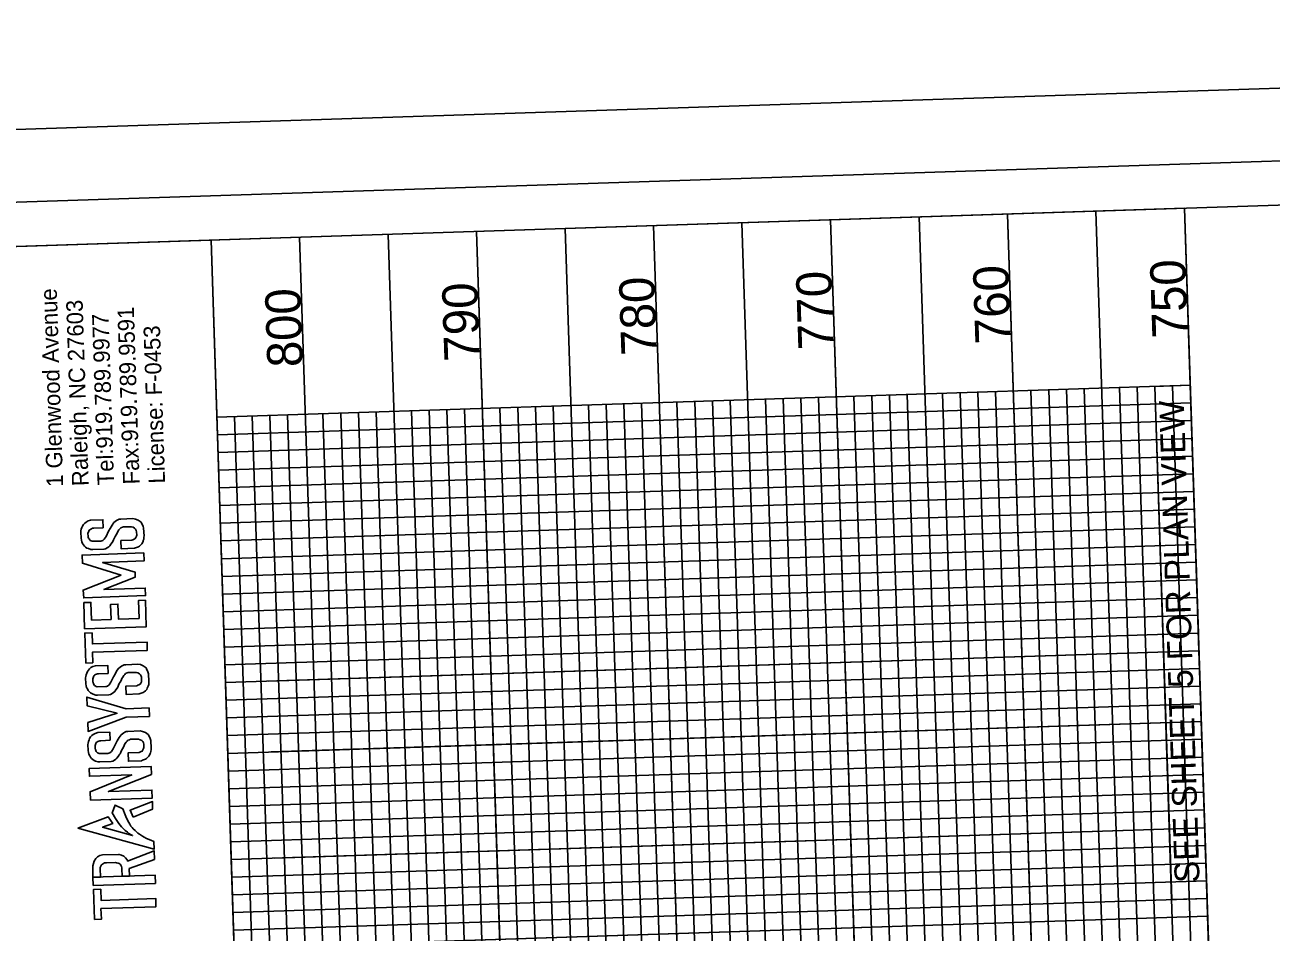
# Model space of a CAD drawing. Extents: x 1627314 to 1628469, y 762309 to 764253.
# Drawn here: x 1627512.6 to 1627864.5, y 763788.2 to 764044.4 of the extents above; entities that cross this region are included whole.
import ezdxf

# ---------------------------------------------------------------- set-up
doc = ezdxf.new("R2010")
doc.units = 0
for name, color, linetype in [('Exist Vertical Profile Vertical Axis Label', 7, 'Continuous'), ('Old_Level_2', 7, 'Continuous'), ('Old_Level_58', 7, 'Continuous'), ('Prop DSN Text', 7, 'Continuous'), ('Prop Grid Mask', 7, 'Continuous'), ('Sheet DOT Grid CELL', 7, 'Continuous'), ('Sheet Layout Profile Border Port 1', 7, 'Continuous'), ('Sheet Plot Border Inside CELL', 7, 'Continuous'), ('Sheet Plot Border Outside CELL', 7, 'Continuous'), ('Sheet Profile CELL', 7, 'Continuous'), ('Sheet Profile Grid Major CELL', 7, 'Continuous'), ('Sheet Profile Grid Middle CELL', 7, 'Continuous'), ('Sheet Profile Grid Minor CELL', 7, 'Continuous')]:
    doc.layers.add(name, color=color, linetype=linetype)

msp = doc.modelspace()

# ---------------------------------------------------------------- linework, layer by layer
at = {"layer": 'Old_Level_2'}
for points in [[(1627534.7, 763902.32), (1627534.62, 763904.63), (1627531.15, 763904.51), (1627530.45, 763904.29), (1627529.87, 763903.99), (1627529.49, 763903.68), (1627529.15, 763903.3), (1627528.88, 763902.85), (1627528.72, 763902.42), (1627528.72, 763902.42), (1627528.54, 763901.95), (1627528.44, 763901.47), (1627528.37, 763901.14), (1627528.46, 763899.4), (1627528.57, 763898.87), (1627528.66, 763898.42), (1627528.92, 763897.96), (1627529.14, 763897.57), (1627529.44, 763897.18), (1627529.76, 763896.88), (1627530.13, 763896.65), (1627530.53, 763896.47), (1627531.24, 763896.24), (1627531.76, 763896.2), (1627534.92, 763896.31), (1627535.4, 763896.44), (1627535.88, 763896.68), (1627536.28, 763896.99), (1627536.58, 763897.29), (1627536.92, 763897.76), (1627537.25, 763898.22), (1627537.46, 763898.51), (1627537.67, 763899), (1627537.88, 763899.49), (1627538.12, 763899.89), (1627538.39, 763900.34), (1627538.64, 763900.87), (1627538.84, 763901.31), (1627539.14, 763901.75), (1627539.43, 763902.07), (1627539.66, 763902.33), (1627540.13, 763902.5), (1627540.43, 763902.6), (1627542.67, 763902.64), (1627543.16, 763902.5), (1627543.58, 763902.27), (1627543.88, 763901.95), (1627544.06, 763901.6), (1627544.14, 763901.26), (1627544.19, 763900.3), (1627544.11, 763899.97), (1627543.93, 763899.64), (1627543.75, 763899.3), (1627543.42, 763899.15), (1627543.09, 763899), (1627542.82, 763898.88), (1627539.71, 763898.74), (1627539.82, 763896.4), (1627543.52, 763896.57), (1627543.8, 763896.69), (1627544.65, 763896.99), (1627544.94, 763897.18), (1627545.25, 763897.44), (1627545.61, 763897.83), (1627545.8, 763898.14), (1627545.96, 763898.58), (1627546.03, 763898.74), (1627546.19, 763899.18), (1627546.23, 763899.72), (1627546.25, 763900.11), (1627546.13, 763902.25), (1627545.97, 763902.84), (1627545.57, 763903.65), (1627545.43, 763903.93), (1627544.62, 763904.52), (1627543.83, 763904.83), (1627543.11, 763904.96), (1627539.69, 763904.8), (1627539.22, 763904.77), (1627538.85, 763904.63), (1627538.5, 763904.43), (1627537.76, 763903.86), (1627537.23, 763903.14), (1627536.68, 763902.14), (1627536.26, 763901.39), (1627535.54, 763899.9), (1627535.01, 763899.13), (1627534.59, 763898.78), (1627534.31, 763898.7), (1627534.03, 763898.61), (1627531.6, 763898.58), (1627531.34, 763898.69), (1627531.08, 763898.81), (1627530.93, 763898.98), (1627530.72, 763899.21), (1627530.61, 763899.46), (1627530.49, 763899.72), (1627530.52, 763899.86), (1627530.44, 763899.88), (1627530.42, 763900.84), (1627530.53, 763901.12), (1627530.63, 763901.4), (1627530.73, 763901.68), (1627530.91, 763901.81), (1627531.19, 763902.01), (1627531.46, 763902.11), (1627531.73, 763902.21), (1627532.04, 763902.21)], [(1627539.83, 763888.95), (1627529.04, 763884.78), (1627529.22, 763882.58), (1627546.67, 763883.23), (1627546.59, 763885.34), (1627534.92, 763884.9), (1627543.79, 763888.46), (1627543.78, 763889.81), (1627534.56, 763892.58), (1627546.27, 763893), (1627546.19, 763895.28), (1627528.78, 763894.65), (1627528.86, 763892.35)], [(1627529.23, 763881.22), (1627529.48, 763873.84), (1627546.89, 763874.43), (1627546.64, 763881.9), (1627544.67, 763881.83), (1627544.84, 763876.79), (1627539, 763876.59), (1627538.86, 763880.8), (1627536.79, 763880.73), (1627536.93, 763876.49), (1627531.44, 763876.3), (1627531.27, 763881.31)], [(1627529.79, 763864.16), (1627529.51, 763872.62), (1627531.58, 763872.69), (1627531.69, 763869.58), (1627547.1, 763870.1), (1627547.18, 763867.75), (1627531.66, 763867.23), (1627531.76, 763864.26)], [(1627536.08, 763861.21), (1627536.01, 763863.52), (1627532.53, 763863.4), (1627531.83, 763863.18), (1627531.25, 763862.88), (1627530.87, 763862.57), (1627530.53, 763862.19), (1627530.26, 763861.74), (1627530.1, 763861.31), (1627530.1, 763861.31), (1627529.93, 763860.84), (1627529.82, 763860.36), (1627529.75, 763860.03), (1627529.84, 763858.29), (1627529.95, 763857.76), (1627530.04, 763857.31), (1627530.3, 763856.85), (1627530.52, 763856.46), (1627530.82, 763856.07), (1627531.14, 763855.77), (1627531.52, 763855.54), (1627531.92, 763855.36), (1627532.62, 763855.13), (1627533.14, 763855.09), (1627536.31, 763855.2), (1627536.78, 763855.33), (1627537.26, 763855.58), (1627537.67, 763855.88), (1627537.97, 763856.18), (1627538.3, 763856.65), (1627538.63, 763857.11), (1627538.84, 763857.4), (1627539.05, 763857.89), (1627539.26, 763858.38), (1627539.5, 763858.78), (1627539.77, 763859.23), (1627540.02, 763859.77), (1627540.23, 763860.21), (1627540.53, 763860.65), (1627540.81, 763860.96), (1627541.04, 763861.22), (1627541.52, 763861.39), (1627541.81, 763861.5), (1627544.05, 763861.53), (1627544.54, 763861.39), (1627544.97, 763861.16), (1627545.27, 763860.84), (1627545.44, 763860.49), (1627545.52, 763860.15), (1627545.57, 763859.19), (1627545.49, 763858.87), (1627545.31, 763858.53), (1627545.13, 763858.2), (1627544.8, 763858.04), (1627544.47, 763857.89), (1627544.21, 763857.77), (1627541.1, 763857.63), (1627541.2, 763855.29), (1627544.91, 763855.46), (1627545.19, 763855.58), (1627546.04, 763855.88), (1627546.32, 763856.07), (1627546.63, 763856.33), (1627547, 763856.72), (1627547.18, 763857.03), (1627547.35, 763857.48), (1627547.41, 763857.64), (1627547.58, 763858.07), (1627547.61, 763858.61), (1627547.64, 763859), (1627547.51, 763861.14), (1627547.35, 763861.73), (1627546.95, 763862.54), (1627546.82, 763862.82), (1627546.01, 763863.41), (1627545.21, 763863.72), (1627544.49, 763863.85), (1627541.08, 763863.69), (1627540.6, 763863.66), (1627540.23, 763863.52), (1627539.88, 763863.32), (1627539.14, 763862.75), (1627538.61, 763862.03), (1627538.06, 763861.04), (1627537.64, 763860.28), (1627536.92, 763858.79), (1627536.39, 763858.02), (1627535.98, 763857.67), (1627535.7, 763857.59), (1627535.42, 763857.5), (1627532.98, 763857.47), (1627532.73, 763857.58), (1627532.47, 763857.7), (1627532.31, 763857.87), (1627532.11, 763858.1), (1627531.99, 763858.35), (1627531.87, 763858.61), (1627531.9, 763858.75), (1627531.82, 763858.77), (1627531.81, 763859.73), (1627531.91, 763860.01), (1627532.01, 763860.29), (1627532.11, 763860.57), (1627532.3, 763860.7), (1627532.57, 763860.9), (1627532.84, 763861), (1627533.12, 763861.1), (1627533.42, 763861.1)], [(1627530.37, 763847.41), (1627530.45, 763844.88), (1627541.21, 763848.85), (1627547.75, 763849.09), (1627547.66, 763851.48), (1627541.17, 763851.24), (1627530.09, 763854.54), (1627530.24, 763852.05), (1627538.66, 763850.01)], [(1627536.72, 763842.35), (1627536.64, 763844.65), (1627533.16, 763844.54), (1627532.47, 763844.32), (1627531.89, 763844.02), (1627531.51, 763843.71), (1627531.17, 763843.33), (1627530.9, 763842.88), (1627530.74, 763842.45), (1627530.74, 763842.45), (1627530.56, 763841.98), (1627530.45, 763841.5), (1627530.38, 763841.17), (1627530.48, 763839.43), (1627530.59, 763838.9), (1627530.68, 763838.45), (1627530.93, 763837.99), (1627531.16, 763837.6), (1627531.46, 763837.21), (1627531.78, 763836.91), (1627532.15, 763836.68), (1627532.55, 763836.5), (1627533.26, 763836.27), (1627533.77, 763836.23), (1627536.94, 763836.34), (1627537.41, 763836.47), (1627537.9, 763836.71), (1627538.3, 763837.02), (1627538.6, 763837.32), (1627538.93, 763837.78), (1627539.27, 763838.25), (1627539.48, 763838.54), (1627539.69, 763839.03), (1627539.89, 763839.52), (1627540.13, 763839.92), (1627540.41, 763840.37), (1627540.66, 763840.9), (1627540.86, 763841.34), (1627541.16, 763841.78), (1627541.45, 763842.1), (1627541.68, 763842.36), (1627542.15, 763842.53), (1627542.45, 763842.63), (1627544.68, 763842.67), (1627545.17, 763842.53), (1627545.6, 763842.3), (1627545.9, 763841.98), (1627546.07, 763841.63), (1627546.16, 763841.29), (1627546.21, 763840.33), (1627546.13, 763840), (1627545.95, 763839.67), (1627545.76, 763839.33), (1627545.43, 763839.18), (1627545.1, 763839.03), (1627544.84, 763838.91), (1627541.73, 763838.77), (1627541.84, 763836.43), (1627545.54, 763836.6), (1627545.82, 763836.72), (1627546.67, 763837.02), (1627546.96, 763837.21), (1627547.27, 763837.47), (1627547.63, 763837.86), (1627547.81, 763838.17), (1627547.98, 763838.61), (1627548.04, 763838.77), (1627548.21, 763839.21), (1627548.25, 763839.75), (1627548.27, 763840.14), (1627548.15, 763842.28), (1627547.99, 763842.87), (1627547.59, 763843.68), (1627547.45, 763843.95), (1627546.64, 763844.55), (1627545.84, 763844.86), (1627545.13, 763844.99), (1627541.71, 763844.83), (1627541.24, 763844.8), (1627540.87, 763844.66), (1627540.52, 763844.46), (1627539.78, 763843.89), (1627539.24, 763843.17), (1627538.7, 763842.17), (1627538.28, 763841.42), (1627537.56, 763839.93), (1627537.02, 763839.15), (1627536.61, 763838.81), (1627536.33, 763838.73), (1627536.05, 763838.64), (1627533.62, 763838.61), (1627533.36, 763838.72), (1627533.1, 763838.84), (1627532.94, 763839.01), (1627532.74, 763839.23), (1627532.62, 763839.49), (1627532.51, 763839.75), (1627532.53, 763839.89), (1627532.46, 763839.91), (1627532.44, 763840.86), (1627532.54, 763841.15), (1627532.64, 763841.43), (1627532.74, 763841.71), (1627532.93, 763841.84), (1627533.2, 763842.04), (1627533.48, 763842.14), (1627533.75, 763842.24), (1627534.06, 763842.24)], [(1627531.1, 763825.45), (1627548.55, 763826.04), (1627548.47, 763828.28), (1627536.2, 763827.86), (1627548.35, 763832.72), (1627548.25, 763834.96), (1627530.75, 763834.37), (1627530.83, 763832.19), (1627542.8, 763832.6), (1627531.01, 763827.81)], [(1627527.54, 763817.56), (1627549.08, 763811.6), (1627548.99, 763813.82), (1627548.14, 763814.14), (1627546.97, 763814.67), (1627546.33, 763814.96), (1627545.78, 763815.32), (1627545, 763815.82), (1627544.52, 763816.13), (1627544.12, 763816.5), (1627543.71, 763816.86), (1627543.2, 763817.33), (1627542.92, 763817.74), (1627542.57, 763818.14), (1627542.23, 763818.69), (1627541.93, 763819.17), (1627541.33, 763820.37), (1627540.88, 763821.35), (1627540.27, 763822.98), (1627538.09, 763824.04), (1627537.21, 763821.84), (1627538.15, 763820.23), (1627539.1, 763818.89), (1627539.92, 763817.93), (1627540.37, 763817.42), (1627540.95, 763816.91), (1627541.54, 763816.39), (1627541.97, 763816.01), (1627542.63, 763815.65), (1627543, 763815.45), (1627534.54, 763817.81), (1627537.4, 763818.9), (1627536.08, 763820.75)], [(1627543.15, 763820.69), (1627542.32, 763822.58), (1627548.68, 763825.05), (1627548.67, 763822.95)], [(1627533.93, 763803.74), (1627533.85, 763806.13), (1627533.89, 763806.43), (1627534.04, 763806.84), (1627534.24, 763807.17), (1627534.51, 763807.41), (1627534.83, 763807.58), (1627535.09, 763807.71), (1627535.67, 763807.73), (1627538.16, 763807.82), (1627538.49, 763807.77), (1627538.94, 763807.7), (1627539.23, 763807.58), (1627539.5, 763807.38), (1627539.72, 763807.12), (1627539.89, 763806.7), (1627539.94, 763806.38), (1627539.99, 763806.05), (1627540.07, 763803.95), (1627542.18, 763804.03), (1627542.1, 763806.13), (1627549.18, 763808.74), (1627549.07, 763811.15), (1627541.63, 763808.25), (1627541.48, 763808.63), (1627541.06, 763809.15), (1627540.51, 763809.62), (1627539.87, 763809.95), (1627539.23, 763810.14), (1627539.04, 763810.12), (1627534.48, 763810.01), (1627533.74, 763809.79), (1627533.08, 763809.4), (1627532.62, 763808.98), (1627532.17, 763808.26), (1627531.96, 763807.58), (1627531.76, 763806.89), (1627531.77, 763806.49), (1627531.84, 763803.67)], [(1627531.92, 763801.36), (1627531.84, 763803.67), (1627549.4, 763804.26), (1627549.48, 763801.95)], [(1627532.23, 763791.74), (1627531.95, 763800.2), (1627534.02, 763800.27), (1627534.12, 763797.16), (1627549.54, 763797.68), (1627549.62, 763795.33), (1627534.1, 763794.81), (1627534.2, 763791.84)]]:
    msp.add_lwpolyline(points, close=True, dxfattribs=at)
at = {"layer": 'Old_Level_58'}
msp.add_lwpolyline([(1627507.79, 763781.61), (1627501.25, 763981.49), (1627565.16, 763983.58), (1627571.7, 763783.7)], close=True, dxfattribs=at)
at = {"layer": 'Prop Grid Mask'}
msp.add_lwpolyline([(1627831.66, 763942.29), (1627836.4, 763797.36), (1627846.39, 763797.69), (1627841.65, 763942.61)], close=True, dxfattribs=at)
at = {"layer": 'Sheet DOT Grid CELL'}
for p, q in [((1627740.07, 763989.32), (1627789.11, 762490.12)), ((1627790.04, 763990.95), (1627839.08, 762491.75)), ((1627640.12, 763986.05), (1627689.16, 762486.85)), ((1627690.1, 763987.68), (1627739.13, 762488.48)), ((1627590.15, 763984.41), (1627639.19, 762485.21)), ((1627841.65, 763942.61), (1627566.8, 763933.62)), ((1627843.28, 763892.64), (1627568.43, 763883.65)), ((1627844.92, 763842.67), (1627570.07, 763833.68)), ((1627846.55, 763792.69), (1627484.3, 763780.84))]:
    msp.add_line(p, q, dxfattribs=at)
at = {"layer": 'Sheet Layout Profile Border Port 1'}
msp.add_lwpolyline([(1627548.65, 762532.28), (1627887.42, 762543.36), (1627841.65, 763942.61), (1627566.8, 763933.62)], dxfattribs=at)
at = {"layer": 'Sheet Plot Border Inside CELL'}
msp.add_lwpolyline([(1628446.34, 762357.53), (1628391.86, 764023.14), (1627337.33, 763988.65), (1627391.81, 762323.04)], close=True, dxfattribs=at)
at = {"layer": 'Sheet Plot Border Outside CELL'}
msp.add_lwpolyline([(1628469.21, 762345.27), (1628413.63, 764044.37), (1627314.22, 764008.4), (1627369.79, 762309.31)], close=True, dxfattribs=at)
at = {"layer": 'Sheet Profile CELL'}
msp.add_line((1627889.05, 762493.39), (1627840.02, 763992.59), dxfattribs=at)
msp.add_lwpolyline([(1627340.28, 763976.24), (1627389.32, 762477.04), (1628438.76, 762511.37), (1628389.72, 764010.57)], close=True, dxfattribs=at)
at = {"layer": 'Sheet Profile Grid Major CELL'}
for points in [[(1627566.8, 763933.62), (1627841.65, 763942.61), (1627840.02, 763992.59), (1627490.2, 763981.14)], [(1627740.07, 763989.32), (1627789.11, 762490.12), (1627789.11, 762490.12), (1627839.08, 762491.75), (1627790.04, 763990.95)], [(1627640.12, 763986.05), (1627689.16, 762486.85), (1627739.13, 762488.48), (1627690.1, 763987.68)], [(1627546.71, 763782.88), (1627589.21, 762483.58), (1627639.19, 762485.21), (1627590.15, 763984.41)], [(1627570.07, 763833.68), (1627844.92, 763842.67), (1627843.28, 763892.64), (1627843.28, 763892.64), (1627568.43, 763883.65)], [(1627363.17, 763276.61), (1627361.53, 763326.59), (1627861.27, 763342.93), (1627859.63, 763392.91), (1627359.9, 763376.56), (1627358.26, 763426.53), (1627858, 763442.88), (1627856.36, 763492.85), (1627356.63, 763476.51), (1627354.99, 763526.48), (1627854.73, 763542.83), (1627853.09, 763592.8), (1627353.36, 763576.45), (1627351.73, 763626.43), (1627851.46, 763642.77), (1627849.82, 763692.75), (1627350.09, 763676.4), (1627348.46, 763726.37), (1627848.19, 763742.72), (1627846.55, 763792.69), (1627346.82, 763776.35), (1627345.96, 763802.63)]]:
    msp.add_lwpolyline(points, dxfattribs=at)
at = {"layer": 'Sheet Profile Grid Middle CELL'}
for points in [[(1627715.08, 763988.5), (1627764.12, 762489.3), (1627814.09, 762490.94), (1627765.06, 763990.13)], [(1627815.03, 763991.77), (1627864.07, 762492.57)], [(1627615.14, 763985.23), (1627664.17, 762486.03), (1627714.15, 762487.67), (1627665.11, 763986.86)], [(1627570.88, 763808.69), (1627565.16, 763983.6)], [(1627581.44, 763859.06), (1627844.1, 763867.65), (1627842.47, 763917.63), (1627567.61, 763908.64)], [(1627583.08, 763809.09), (1627845.74, 763817.68), (1627844.1, 763867.65), (1627569.25, 763858.66)], [(1627863.72, 763267.97), (1627862.08, 763317.95), (1627362.35, 763301.6), (1627360.72, 763351.57), (1627860.45, 763367.92), (1627858.81, 763417.89), (1627359.08, 763401.55), (1627357.45, 763451.52), (1627857.18, 763467.87), (1627855.54, 763517.84), (1627355.81, 763501.49), (1627354.18, 763551.47), (1627853.91, 763567.81), (1627852.28, 763617.79), (1627352.54, 763601.44), (1627350.91, 763651.41), (1627850.64, 763667.76), (1627849.01, 763717.73), (1627349.27, 763701.39), (1627347.64, 763751.36), (1627847.37, 763767.71), (1627845.74, 763817.68), (1627570.88, 763808.69)], [(1627521.73, 763782.02), (1627564.23, 762482.76), (1627614.2, 762484.4), (1627570.88, 763808.69)]]:
    msp.add_lwpolyline(points, dxfattribs=at)
at = {"layer": 'Sheet Profile Grid Minor CELL'}
for p, q in [((1627751.7, 763939.67), (1627797.47, 762540.42)), ((1627802.47, 762540.58), (1627756.7, 763939.83)), ((1627761.69, 763940), (1627807.46, 762540.75)), ((1627817.46, 762541.07), (1627771.69, 763940.32)), ((1627776.69, 763940.49), (1627822.45, 762541.24)), ((1627827.45, 762541.4), (1627781.68, 763940.65)), ((1627786.68, 763940.81), (1627832.45, 762541.56)), ((1627842.44, 762541.89), (1627796.67, 763941.14)), ((1627801.67, 763941.3), (1627847.44, 762542.05)), ((1627852.44, 762542.22), (1627806.67, 763941.47)), ((1627811.67, 763941.63), (1627857.44, 762542.38)), ((1627867.43, 762542.71), (1627821.66, 763941.96)), ((1627826.66, 763942.12), (1627872.43, 762542.87)), ((1627877.42, 762543.03), (1627831.66, 763942.29)), ((1627692.52, 762536.99), (1627646.75, 763936.24)), ((1627651.75, 763936.4), (1627697.52, 762537.15)), ((1627702.52, 762537.31), (1627656.75, 763936.56)), ((1627661.75, 763936.73), (1627707.52, 762537.48)), ((1627717.51, 762537.8), (1627671.74, 763937.05)), ((1627676.74, 763937.22), (1627722.51, 762537.97)), ((1627727.51, 762538.13), (1627681.74, 763937.38)), ((1627686.73, 763937.55), (1627732.5, 762538.29)), ((1627742.5, 762538.62), (1627696.73, 763937.87)), ((1627701.73, 763938.04), (1627747.49, 762538.78)), ((1627752.49, 762538.95), (1627706.72, 763938.2)), ((1627711.72, 763938.36), (1627757.49, 762539.11)), ((1627767.48, 762539.44), (1627721.71, 763938.69)), ((1627726.71, 763938.85), (1627772.48, 762539.6)), ((1627731.71, 763939.02), (1627777.48, 762539.76)), ((1627736.71, 763939.18), (1627782.48, 762539.93)), ((1627792.47, 762540.25), (1627746.7, 763939.51)), ((1627576.79, 763933.95), (1627622.56, 762534.7)), ((1627627.56, 762534.86), (1627581.79, 763934.11)), ((1627586.79, 763934.28), (1627632.56, 762535.02)), ((1627642.55, 762535.35), (1627596.78, 763934.6)), ((1627601.78, 763934.77), (1627647.55, 762535.51)), ((1627652.55, 762535.68), (1627606.78, 763934.93)), ((1627611.77, 763935.09), (1627657.54, 762535.84)), ((1627667.54, 762536.17), (1627621.77, 763935.42)), ((1627626.77, 763935.58), (1627672.53, 762536.33)), ((1627677.53, 762536.5), (1627631.76, 763935.75)), ((1627636.76, 763935.91), (1627682.53, 762536.66))]:
    msp.add_line(p, q, dxfattribs=at)
for points in [[(1627836.65, 763942.45), (1627882.42, 762543.2)], [(1627567.12, 763923.63), (1627841.98, 763932.62), (1627841.81, 763937.62), (1627566.96, 763928.62)], [(1627566.71, 763783.49), (1627607.57, 762534.21), (1627617.56, 762534.53), (1627571.79, 763933.79)], [(1627567.45, 763913.63), (1627842.3, 763922.62), (1627842.14, 763927.62), (1627567.29, 763918.63)], [(1627567.94, 763898.64), (1627842.79, 763907.63), (1627842.63, 763912.63), (1627567.78, 763903.64)], [(1627568.27, 763888.65), (1627843.12, 763897.64), (1627842.96, 763902.63), (1627568.1, 763893.64)], [(1627568.76, 763873.65), (1627843.61, 763882.64), (1627843.45, 763887.64), (1627568.6, 763878.65)], [(1627569.09, 763863.66), (1627843.94, 763872.65), (1627843.78, 763877.65), (1627568.92, 763868.66)], [(1627569.58, 763848.67), (1627844.43, 763857.66), (1627844.27, 763862.66), (1627569.41, 763853.66)], [(1627582.1, 763839.07), (1627844.76, 763847.66), (1627844.59, 763852.66), (1627569.74, 763843.67)], [(1627570.23, 763828.65), (1627845.04, 763837.57), (1627844.87, 763842.56), (1627844.76, 763847.66), (1627569.9, 763838.67)], [(1627570.72, 763813.69), (1627845.57, 763822.68), (1627845.57, 763822.68), (1627845.41, 763827.67), (1627845.25, 763832.67), (1627570.39, 763823.68)], [(1627570.56, 763818.68), (1627845.41, 763827.67)], [(1627571.21, 763798.69), (1627846.06, 763807.68), (1627845.9, 763812.68), (1627571.05, 763803.69)], [(1627571.54, 763788.7), (1627846.39, 763797.69), (1627846.23, 763802.69), (1627571.37, 763793.7)]]:
    msp.add_lwpolyline(points, dxfattribs=at)

# ---------------------------------------------------------------- texts
at = {"layer": 'Exist Vertical Profile Vertical Axis Label'}
for s, p in [('760', (1627790.99, 763954.39)), ('750', (1627840.96, 763956.03)), ('780', (1627691.04, 763951.13)), ('770', (1627741.01, 763952.76)), ('800', (1627591.09, 763947.86)), ('790', (1627641.07, 763949.49))]:
    msp.add_text(s, height=10, rotation=91.8735, dxfattribs=at).set_placement(p)
at = {"layer": 'Old_Level_2'}
for s, p in [('1 Glenwood Avenue', (1627523.43, 763913.98)), ('Raleigh, NC 27603', (1627530.62, 763914.21)), ('Fax:919.789.9591', (1627545.01, 763914.68)), ('Tel:919.789.9977 ', (1627537.81, 763914.45)), ('License: F-0453', (1627552.2, 763914.92))]:
    msp.add_text(s, height=4.6576, rotation=91.8735, dxfattribs=at).set_placement(p)
at = {"layer": 'Prop DSN Text'}
msp.add_text('SEE SHEET 5 FOR PLAN VIEW', height=7, rotation=91.8735, dxfattribs=at).set_placement((1627844.29, 763802.2))

doc.saveas('drawing.dxf')
